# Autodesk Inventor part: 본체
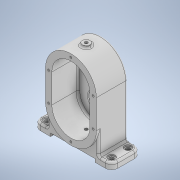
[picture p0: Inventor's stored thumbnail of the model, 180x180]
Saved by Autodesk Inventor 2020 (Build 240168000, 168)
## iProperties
Created: 2021-05
Part Number: 본체
Material: 일반
Document SubType Name: Modeling
Designer: Owner
Density: 1 g/cm^3
Appearance: 기본값
Author: Owner
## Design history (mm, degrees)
sketch "스케치1"
  geometry: L1 (-40, 22.5)-(40, 22.5); L2 (40, 22.5)-(40, -22.5); L3 (40, -22.5)-(-40, -22.5); L4 (-40, -22.5)-(-40, 22.5); L5 (-40, 22.5)-(40, -22.5); L6 (40, 22.5)-(-40, -22.5); C1 r 40 at (0, 22.5); C2 r 40 at (0, -22.5); 5 further points
  constraints: 12 end point, 4 midpoint, 2 centre point, 2 parallel, 1 horizontal, 1 perpendicular
  dimensions: "d0" = 80 distance of L2.end L3.end; "d1" = 45 distance of L1.end L2.end; "d2" = 80 diameter of C1; "d3" = 80 diameter of C2
extrude "돌출1" new body sketch "스케치1" distance "d4" = 49; taper "d5" = 0 deg
sketch "스케치2"
  geometry: L1 (-40, 22.5)-(-40, -22.5) reference; L2 (40, -22.5)-(40, 22.5) reference; L3 (30, 22.5)-(30, -22.5); L4 (-30, 22.5)-(-30, -22.5); A1 r 40 centre (0, 22.5) between (40, 22.5) and (-40, 22.5) reference; A2 r 40 centre (0, -22.5) between (-40, -22.5) and (40, -22.5) reference; A3 r 30 centre (0, 22.5) between (30, 22.5) and (-30, 22.5); A4 r 30 centre (0, -22.5) between (30, -22.5) and (-30, -22.5); 3 further points
  constraints: 4 end point, 4 point on circle, 2 centre point, 2 coincident, 2 tangent, 1 parallel
  dimensions: "d6" = 60 diameter of A3; "d7" = 60 diameter of A4
extrude "돌출2" cut sketch "스케치2" distance "d8" = 41; taper "d9" = 0 deg
sketch "스케치3"
  geometry: L1 (30, 22.5)-(30, -22.5) reference; L2 (-30, -22.5)-(-30, 22.5) reference; C1 r 14 at (0, 22.5); C2 r 14 at (0, -22.5); A1 r 30 centre (0, -22.5) between (-30, -22.5) and (30, -22.5) reference; A2 r 30 centre (0, 22.5) between (30, 22.5) and (-30, 22.5) reference; 1 further point
  constraints: 2 centre point, 2 coincident
  dimensions: "d10" = 28 diameter of C1; "d11" = 28 diameter of C2
extrude "돌출3" cut sketch "스케치3" distance "d12" = 8; taper "d13" = 0 deg
sketch "스케치6"
  geometry: L1 (40, 22.5)-(40, -22.5) reference; L2 (-40, -22.5)-(-40, 22.5) reference; L3 (-26, 22.5)-(26, 22.5); L4 (26, 22.5)-(26, -22.5); L5 (26, -22.5)-(-26, -22.5); L6 (-26, -22.5)-(-26, 22.5); L7 (-26, 22.5)-(26, -22.5); L8 (26, 22.5)-(-26, -22.5); C1 r 14 at (0, -22.5) reference; C2 r 14 at (0, 22.5) reference; C3 r 26 at (0, 22.5); C4 r 26 at (0, -22.5); A1 r 40 centre (0, 22.5) between (40, 22.5) and (-40, 22.5) reference; A2 r 40 centre (0, -22.5) between (-40, -22.5) and (40, -22.5) reference; 7 further points
  constraints: 12 end point, 3 coincident, 3 midpoint, 2 centre point, 2 parallel, 1 horizontal, 1 perpendicular
  dimensions: "d23" = 52 diameter of C3; "d24" = 52 diameter of C4; "d25" = 52 distance of L4.end L5.end; "d26" = 45 distance of L3.end L4.end
extrude "돌출5" join sketch "스케치6" distance "d27" = 8; taper "d28" = 0 deg
sketch "스케치7"
  geometry: L1 (0, 0)-(0, 15); L2 (-26, -7.5)-(26, -7.5); L3 (26, -7.5)-(26, -22.5); L4 (26, -22.5)-(-26, -22.5); L5 (-26, -22.5)-(-26, -7.5); L6 (-26, -7.5)-(26, -22.5); L7 (26, -7.5)-(-26, -22.5); L8 (-26, 22.5)-(-26, -22.5) reference; L9 (26, -22.5)-(26, 22.5) reference; A1 r 26 centre (0, -22.5) between (-26, -22.5) and (26, -22.5) reference; A2 r 26 centre (0, 22.5) between (26, 22.5) and (-26, 22.5) reference; A3 r 26 centre (0, -22.5) between (22.005, -8.652) and (21.237, -7.5); A4 r 26 centre (0, -22.5) between (-21.237, -7.5) and (-22.005, -8.652); A5 r 26 centre (0, -22.5) between (-26, -22.5) and (26, -22.5); 4 further points
  constraints: 14 end point, 6 point on circle, 3 centre point, 3 midpoint, 3 point on line, 2 coincident, 2 parallel, 1 horizontal, 1 perpendicular, 1 vertical
  dimensions: "d29" = 15 distance of L1.start L1.end; "d30" = 52 distance of L3.end L4.end; "d31" = 15 distance of L2.end L3.end
extrude "돌출6" join sketch "스케치7" distance "d33" = 3; taper "d34" = 0 deg
sketch "스케치8"
  geometry: L1 (-26, -7.5)-(26, -7.5) reference; L2 (26, -7.5)-(26, 22.5) reference; L3 (-26, 22.5)-(-26, -7.5) reference; C1 r 11 at (0, 22.5); C2 r 14 at (0, 22.5); A1 r 26 centre (0, 22.5) between (26, 22.5) and (-26, 22.5) reference; 1 further point
  constraints: 2 centre point, 2 coincident
  dimensions: "d35" = 22 diameter of C1; "d36" = 28 diameter of C2
  node "투영된 루프6"
extrude "돌출7" cut sketch "스케치8" extent not by distance; stored distance "d37" = 0; taper "d38" = 0 deg
extrude "돌출8" cut sketch "스케치8" distance "d39" = 4; taper "d40" = 0 deg
sketch "스케치9"
  geometry: C1 r 14 at (0, 0) reference; C2 r 10 at (0, 0); 1 further point
  constraints: 1 centre point, 1 coincident
  dimensions: "d41" = 20 diameter of C2
extrude "돌출9" cut sketch "스케치9" distance "d42" = 4; taper "d43" = 0 deg
node "작업 평면1"
sketch "스케치10"
  geometry: L1 (61, 0)-(-61, 0); L2 (-61, 0)-(-61, 46); L3 (-61, 46)-(61, 46); L4 (61, 46)-(61, 0); L5 (61, 0)-(-61, 46); L6 (-61, 0)-(61, 46); L7 (40, 0)-(-40, 0) reference; L8 (-40, 0)-(40, 0); L9 (40, 0)-(40, 46); L10 (40, 46)-(-40, 46); L11 (-40, 46)-(-40, 0); L12 (-40, 0)-(40, 46); L13 (40, 0)-(-40, 46); 9 further points
  constraints: 24 end point, 8 midpoint, 4 parallel, 2 horizontal, 2 perpendicular
  dimensions: "d45" = 122 distance of L2.end L3.end; "d46" = 46 distance of L1.end L2.end; "d49" = 80 distance of L9.end L10.end; "d50" = 46 distance of L8.end L9.end
extrude "돌출10" join sketch "스케치10" distance "d47" = 10; taper "d48" = 0 deg
extrude "돌출11" cut sketch "스케치10" stored distance "d51" = 10; taper "d52" = 0 deg
extrude "돌출12" join sketch "스케치10" stored distance "d53" = 10; taper "d54" = 0 deg
sketch "스케치11"
  geometry: L1 (-183.904, -47)-(-183.904, -42); L2 (-61, -37)-(-40, -37) reference; L3 (-61, -47)-(-61, -37) reference; L4 (-61, -47)-(61, -47) reference; L5 (61, -47)-(61, -37) reference; L6 (40, -37)-(61, -37) reference; L7 (40, -37)-(40, 0) reference; L8 (-40, -37)-(-40, 0) reference; L9 (-35, -42)-(35, -42); L10 (35, -42)-(35, -52); L11 (35, -52)-(-35, -52); L12 (-35, -52)-(-35, -42); L13 (61, -47)-(-61, -47) reference; L14 (-35, -42)-(35, -52); L15 (35, -42)-(-35, -52); L16 (-35, -47)-(35, -47); A1 r 40 centre (0, 0) between (-40, 0) and (40, 0) reference; 6 further points
  constraints: 16 end point, 5 midpoint, 2 parallel, 2 point on line, 1 horizontal, 1 perpendicular
  dimensions: "d57" = 70 distance of L10.end L11.end; "d59" = 5 distance between parallel lines of L9 L16
extrude "돌출13" cut sketch "스케치11" extent not by distance; stored distance "d60" = 0; taper "d61" = 0 deg
sketch "스케치12"
  geometry: 1 further point
sketch "스케치13"
  geometry: L1 (70, -46)-(0, -46) reference; L2 (70, 0)-(70, -46) reference; L3 (0, 0)-(70, 0) reference; L4 (0, 0)-(0, -46) reference; L5 (75, 0)-(-5, 0) reference; L6 (35, 0)-(35, -21); C1 r 6 at (35, -21); 2 further points
  constraints: 2 coincident, 2 end point, 1 centre point, 1 midpoint, 1 vertical
  dimensions: "d62" = 21 distance of L6.start L6.end; "d63" = 12 diameter of C1
  node "투영된 루프9"
extrude "돌출14" cut sketch "스케치13" distance "d64" = 1; taper "d65" = 0 deg
hole "구멍1" sketch "스케치13" diameter "d66" = 4.917; stored, may be unused: countersink angle "d70" = 90 deg, drill point angle "d72" = 118 deg; dims "d67" = 12, "d68" = 4, "d69" = 2, "d71" = 17.1
node "작업 평면2"
sketch "스케치14"
  geometry: C1 r 6 at (0, 25); 3 further points
  constraints: 1 centre point, 1 coincident, 1 horizontal alignment, 1 other
  dimensions: "d74" = 12 diameter of C1
extrude "돌출15" join sketch "스케치14" stored distance "d75" = 1; taper "d76" = 0 deg
sketch "스케치15"
  geometry: L1 (0, 0)-(0, 57.5); L2 (0, 0)-(0, -57.5); 2 further points
  constraints: 4 end point, 2 coincident, 2 vertical
  dimensions: "d77" = 57.5 distance of L1.start L1.end; "d78" = 57.5 distance of L1.start L2.end
hole "구멍2" sketch "스케치15" diameter "d79" = 3.242; stored, may be unused: countersink angle "d83" = 90 deg, drill point angle "d85" = 118 deg; dims "d80" = 8, "d81" = 4, "d82" = 2, "d84" = 10
hole "구멍3" sketch "스케치15" diameter "d92" = 3.242; stored, may be unused: countersink angle "d96" = 90 deg, drill point angle "d98" = 118 deg; dims "d93" = 8, "d94" = 4, "d95" = 2, "d97" = 10
fillet "모깎기1" dims "d105" = 10
sketch "스케치16"
  geometry: L1 (-40, 0)-(-51, 0) reference; L2 (-61, -10)-(-61, -36) reference; C1 r 5.5 at (-51, -10); C2 r 3.3 at (-51, -10); 1 further point
  constraints: 2 centre point, 1 coincident
  dimensions: "d106" = 11 diameter of C1; "d107" = 6.6 diameter of C2; "d108" = 10 distance from line of C1.centre L1; "d109" = 10 distance from line of C1.centre L2
extrude "돌출16" cut sketch "스케치16" distance "d110" = 2; taper "d111" = 0 deg
extrude "돌출17" cut sketch "스케치16" extent not by distance; stored distance "d112" = 0; taper "d113" = 0 deg
fillet "모깎기2" dims "d123" = 3
fillet "모깎기3" dims "d124" = 3
fillet "모깎기4" dims "d125" = 0.3
chamfer "모따기1" distance "d126" = 1; stored, may be unused: second distance "d127" = 2, angle "d128" = 45 deg
sketch "스케치17"
  geometry: L1 (0, 22.5)-(0, 42.5); C1 r 11 at (0, 22.5) reference; 2 further points
  constraints: 2 end point, 1 coincident, 1 vertical
  dimensions: "d129" = 20 distance of L1.start L1.end
hole "구멍4" sketch "스케치17" at (0, 42.5) diameter "d130" = 3.242; stored, may be unused: countersink angle "d134" = 90 deg, drill point angle "d136" = 118 deg; dims "d131" = 8, "d132" = 4, "d133" = 2, "d135" = 10
node "솔리드1"
pattern_circular "원형 패턴1" dims angle "d87" = 90 deg
pattern_circular "원형 패턴2" dims angle "d90" = -90 deg
pattern_circular "원형 패턴3" dims angle "d100" = 90 deg
pattern_circular "원형 패턴4" dims angle "d103" = -90 deg
pattern_linear "직사각형 패턴1" dims "d116" = 26
pattern_linear "직사각형 패턴2" dims "d119" = 102
pattern_linear "직사각형 패턴3" dims "d122" = 26
pattern_circular "원형 패턴5" dims angle "d138" = 360 deg
node "투영된 루프1"
node "투영된 루프2"
node "투영된 루프4"
node "투영된 루프5"
node "투영된 루프7"
node "투영된 루프8"
feature "A9D066F2-1C7D-4E18-AEED-F7BC21143FA4" dims "d79" = 3.242, "d80" = 8, "d81" = 4, "d82" = 2, "d83" = 90 deg, "d84" = 10, "d85" = 118 deg
other parameters: "d32" = 52, "d44" = -69.5, "d73" = 65.5
